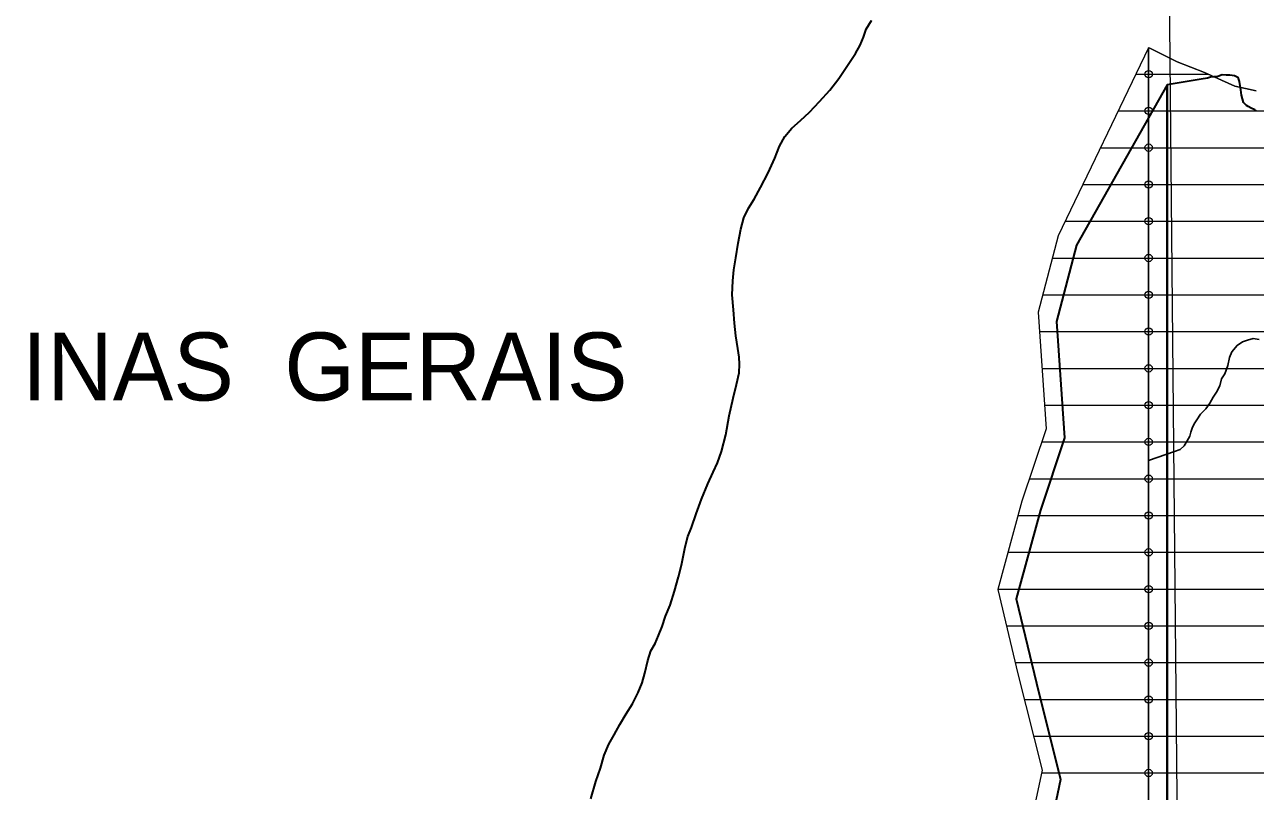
# Model space of a CAD drawing. Extents: x -10.5 to 30.8, y 18.4 to 58.7.
# Drawn here: x -1.4 to 5.3, y 50.15 to 54.32 of the extents above; entities that cross this region are included whole.
import ezdxf

# ---------------------------------------------------------------- set-up
doc = ezdxf.new("R2010")
doc.units = 0
doc.header["$LTSCALE"] = 0.08
doc.header["$PDMODE"] = 32
doc.header["$PDSIZE"] = 0.04
doc.linetypes.add('DASH_DOUBLE_DOT', pattern=[9.2, 5, -1.2, 0.3, -1.2, 0.3, -1.2])
for name, color, linetype, lineweight in [('20', 7, 'DASH_DOUBLE_DOT', 35), ('29', 7, 'Continuous', 13), ('43', 7, 'Continuous', 13), ('48', 7, 'Continuous', 35), ('52', 7, 'Continuous', 13), ('9', 7, 'Continuous', 25)]:
    doc.layers.add(name, color=color, linetype=linetype, lineweight=lineweight)
doc.layers.add('56', color=7, linetype='Continuous')

msp = doc.modelspace()

# ---------------------------------------------------------------- linework, layer by layer
at = {"layer": '20'}
msp.add_lwpolyline([(1.68376, 50.11473), (1.71233, 50.20779), (1.73621, 50.28075), (1.75763, 50.35117), (1.78172, 50.41162), (1.81099, 50.46217), (1.84269, 50.51775), (1.87687, 50.57588), (1.91108, 50.63151), (1.94271, 50.6921), (1.9644, 50.74501), (1.9786, 50.79779), (1.99502, 50.86562), (2.01171, 50.91844), (2.03364, 50.95885), (2.053, 51.00171), (2.07224, 51.05208), (2.0914, 51.10745), (2.11549, 51.16791), (2.13933, 51.24337), (2.16062, 51.32129), (2.17714, 51.38412), (2.18642, 51.42931), (2.19805, 51.48455), (2.2122, 51.53983), (2.23142, 51.5902), (2.25782, 51.6632), (2.28659, 51.74376), (2.32036, 51.82689), (2.34942, 51.88994), (2.37369, 51.94039), (2.39521, 52.00331), (2.41881, 52.09378), (2.43717, 52.19667), (2.45817, 52.29209), (2.47699, 52.36747), (2.491, 52.43025), (2.49272, 52.47782), (2.4921, 52.51533), (2.48377, 52.56272), (2.47256, 52.63258), (2.46642, 52.70001), (2.46019, 52.77246), (2.45379, 52.8549), (2.45756, 52.93002), (2.46158, 52.99013), (2.47304, 53.05537), (2.48677, 53.13567), (2.50056, 53.21095), (2.51708, 53.27378), (2.5413, 53.32674), (2.57313, 53.37482), (2.60722, 53.43795), (2.64855, 53.51872), (2.68489, 53.5969), (2.7114, 53.66241), (2.74065, 53.71545), (2.77753, 53.76111), (2.82454, 53.80195), (2.87398, 53.84784), (2.92822, 53.90632), (2.98494, 53.96734), (3.03408, 54.03073), (3.08058, 54.10158), (3.12467, 54.16739), (3.14901, 54.21284), (3.16838, 54.2557), (3.18274, 54.29848), (3.21204, 54.34652)], dxfattribs=at)
at = {"layer": '29'}
msp.add_lwpolyline([(3.21204, 54.34652), (3.18274, 54.29848), (3.16838, 54.2557), (3.14901, 54.21284), (3.12467, 54.16739), (3.08058, 54.10158), (3.03408, 54.03073), (2.98494, 53.96734), (2.92822, 53.90632), (2.87398, 53.84784), (2.82454, 53.80195), (2.77753, 53.76111), (2.74065, 53.71545), (2.7114, 53.66241), (2.68489, 53.5969), (2.64855, 53.51872), (2.60722, 53.43795), (2.57313, 53.37482), (2.5413, 53.32674), (2.51708, 53.27378), (2.50056, 53.21095), (2.48677, 53.13567), (2.47304, 53.05537), (2.46158, 52.99013), (2.45756, 52.93002), (2.45379, 52.8549), (2.46019, 52.77246), (2.46642, 52.70001), (2.47256, 52.63258), (2.48377, 52.56272), (2.4921, 52.51533), (2.49272, 52.47782), (2.491, 52.43025), (2.47699, 52.36747), (2.45817, 52.29209), (2.43717, 52.19667), (2.41881, 52.09378), (2.39521, 52.00331), (2.37369, 51.94039), (2.34942, 51.88994), (2.32036, 51.82689), (2.28659, 51.74376), (2.25782, 51.6632), (2.23142, 51.5902), (2.2122, 51.53983), (2.19805, 51.48455), (2.18642, 51.42931), (2.17714, 51.38412), (2.16062, 51.32129), (2.13933, 51.24337), (2.11549, 51.16791), (2.0914, 51.10745), (2.07224, 51.05208), (2.053, 51.00171), (2.03364, 50.95885), (2.01171, 50.91844), (1.99502, 50.86562), (1.9786, 50.79779), (1.9644, 50.74501), (1.94271, 50.6921), (1.91108, 50.63151), (1.87687, 50.57588), (1.84269, 50.51775), (1.81099, 50.46217), (1.78172, 50.41162), (1.75763, 50.35117), (1.73621, 50.28075), (1.71233, 50.20779), (1.68376, 50.11473)], dxfattribs=at)
at = {"layer": '29', "linetype": 'DASH_DOUBLE_DOT', "lineweight": 35}
msp.add_lwpolyline([(1.68376, 50.11473), (1.71233, 50.20779), (1.73621, 50.28075), (1.75763, 50.35117), (1.78172, 50.41162), (1.81099, 50.46217), (1.84269, 50.51775), (1.87687, 50.57588), (1.91108, 50.63151), (1.94271, 50.6921), (1.9644, 50.74501), (1.9786, 50.79779), (1.99502, 50.86562), (2.01171, 50.91844), (2.03364, 50.95885), (2.053, 51.00171), (2.07224, 51.05208), (2.0914, 51.10745), (2.11549, 51.16791), (2.13933, 51.24337), (2.16062, 51.32129), (2.17714, 51.38412), (2.18642, 51.42931), (2.19805, 51.48455), (2.2122, 51.53983), (2.23142, 51.5902), (2.25782, 51.6632), (2.28659, 51.74376), (2.32036, 51.82689), (2.34942, 51.88994), (2.37369, 51.94039), (2.39521, 52.00331), (2.41881, 52.09378), (2.43717, 52.19667), (2.45817, 52.29209), (2.47699, 52.36747), (2.491, 52.43025), (2.49272, 52.47782), (2.4921, 52.51533), (2.48377, 52.56272), (2.47256, 52.63258), (2.46642, 52.70001), (2.46019, 52.77246), (2.45379, 52.8549), (2.45756, 52.93002), (2.46158, 52.99013), (2.47304, 53.05537), (2.48677, 53.13567), (2.50056, 53.21095), (2.51708, 53.27378), (2.5413, 53.32674), (2.57313, 53.37482), (2.60722, 53.43795), (2.64855, 53.51872), (2.68489, 53.5969), (2.7114, 53.66241), (2.74065, 53.71545), (2.77753, 53.76111), (2.82454, 53.80195), (2.87398, 53.84784), (2.92822, 53.90632), (2.98494, 53.96734), (3.03408, 54.03073), (3.08058, 54.10158), (3.12467, 54.16739), (3.14901, 54.21284), (3.16838, 54.2557), (3.18274, 54.29848), (3.21204, 54.34652)], dxfattribs=at)
at = {"layer": '43'}
for p, q in [((4.719, 48.47183), (4.719, 54.19745)), ((4.719, 48.47183), (4.719, 54.19745)), ((4.65028, 54.0548), (4.719, 54.0548)), ((4.65028, 54.0548), (4.719, 54.0548)), ((4.719, 54.0548), (5.04063, 54.0548)), ((4.55392, 53.8548), (4.719, 53.8548)), ((4.55392, 53.8548), (4.719, 53.8548)), ((4.719, 53.8548), (7.38115, 53.8548)), ((4.45757, 53.6548), (4.719, 53.6548)), ((4.45757, 53.6548), (4.719, 53.6548)), ((4.719, 53.6548), (7.95638, 53.6548)), ((4.36122, 53.4548), (4.719, 53.4548)), ((4.36122, 53.4548), (4.719, 53.4548)), ((4.719, 53.4548), (8.42261, 53.4548)), ((4.26486, 53.2548), (4.719, 53.2548)), ((4.26486, 53.2548), (4.719, 53.2548)), ((4.719, 53.2548), (8.92708, 53.2548)), ((4.19484, 53.0548), (4.719, 53.0548)), ((4.19484, 53.0548), (4.719, 53.0548)), ((4.719, 53.0548), (9.91576, 53.0548)), ((4.14222, 52.8548), (4.719, 52.8548)), ((4.14222, 52.8548), (4.719, 52.8548)), ((4.719, 52.8548), (10.29326, 52.8548)), ((4.12456, 52.6548), (4.719, 52.6548)), ((4.12456, 52.6548), (4.719, 52.6548)), ((4.719, 52.6548), (11.74932, 52.6548)), ((4.13835, 52.4548), (4.719, 52.4548)), ((4.13835, 52.4548), (4.719, 52.4548)), ((4.719, 52.4548), (12.30135, 52.4548)), ((4.15214, 52.2548), (4.719, 52.2548)), ((4.15214, 52.2548), (4.719, 52.2548)), ((4.719, 52.2548), (12.92186, 52.2548)), ((4.1371, 52.0548), (4.719, 52.0548)), ((4.1371, 52.0548), (4.719, 52.0548)), ((4.719, 52.0548), (14.29713, 52.0548)), ((4.07045, 51.8548), (4.719, 51.8548)), ((4.07045, 51.8548), (4.719, 51.8548)), ((4.719, 51.8548), (15.2159, 51.8548)), ((4.00855, 51.6548), (4.719, 51.6548)), ((4.00855, 51.6548), (4.719, 51.6548)), ((4.719, 51.6548), (15.4387, 51.6548)), ((3.95401, 51.4548), (4.719, 51.4548)), ((3.95401, 51.4548), (4.719, 51.4548)), ((4.719, 51.4548), (15.65105, 51.4548)), ((3.89948, 51.2548), (4.719, 51.2548)), ((3.89948, 51.2548), (4.719, 51.2548)), ((4.719, 51.2548), (15.6669, 51.2548)), ((3.94594, 51.0548), (4.719, 51.0548)), ((3.94594, 51.0548), (4.719, 51.0548)), ((4.719, 51.0548), (15.6026, 51.0548)), ((3.99354, 50.8548), (4.719, 50.8548)), ((3.99354, 50.8548), (4.719, 50.8548)), ((4.719, 50.8548), (15.46322, 50.8548)), ((4.04281, 50.6548), (4.719, 50.6548)), ((4.04281, 50.6548), (4.719, 50.6548)), ((4.719, 50.6548), (15.23281, 50.6548)), ((4.09279, 50.4548), (4.719, 50.4548)), ((4.09279, 50.4548), (4.719, 50.4548)), ((4.719, 50.4548), (15.1383, 50.4548)), ((4.13608, 50.2548), (4.719, 50.2548)), ((4.13608, 50.2548), (4.719, 50.2548)), ((4.719, 50.2548), (15.00848, 50.2548))]:
    msp.add_line(p, q, dxfattribs=at)
for points in [[(4.719, 54.19745), (4.22652, 53.1752), (4.1173, 52.76008), (4.16099, 52.12647), (4.02993, 51.7332), (3.89886, 51.25254), (4.00808, 50.79372), (4.13914, 50.26936), (4.05177, 49.85424), (3.94255, 49.37357), (4.22652, 49.08954), (4.22652, 47.72402), (4.08453, 47.36352), (3.83333, 46.77361), (3.77873, 46.60975), (3.85518, 46.20555), (3.81149, 45.92152), (3.88794, 45.58287), (4.43403, 45.27699)], [(4.719, 54.19745), (4.22652, 53.1752), (4.1173, 52.76008), (4.16099, 52.12647), (4.02993, 51.7332), (3.89886, 51.25254), (4.00808, 50.79372), (4.13914, 50.26936), (4.05177, 49.85424), (3.94255, 49.37357), (4.22652, 49.08954), (4.22652, 47.72402), (4.08453, 47.36352), (3.83333, 46.77361), (3.77873, 46.60975), (3.85518, 46.20555), (3.81149, 45.92152), (3.88794, 45.58287), (4.43403, 45.27699)], [(4.719, 54.19745), (4.22652, 53.1752), (4.1173, 52.76008), (4.16099, 52.12647), (4.02993, 51.7332), (3.89886, 51.25254), (4.00808, 50.79372), (4.13914, 50.26936), (4.05177, 49.85424), (3.94255, 49.37357), (4.22652, 49.08954), (4.22652, 47.72402), (3.95893, 47.06856), (3.80603, 46.69168), (3.8004, 46.59979), (3.80803, 46.4548), (3.85518, 46.20555), (3.83333, 46.06354), (3.81149, 45.92152), (3.88794, 45.58287)], [(4.719, 54.19745), (4.22652, 53.1752), (4.1173, 52.76008), (4.16099, 52.12647), (4.02993, 51.7332), (3.89886, 51.25254), (4.00808, 50.79372), (4.13914, 50.26936), (4.05177, 49.85424), (3.94255, 49.37357), (4.22652, 49.08954), (4.22652, 47.72402), (3.95893, 47.06856), (3.80603, 46.69168), (3.8004, 46.59979), (3.80803, 46.4548), (3.85518, 46.20555), (3.83333, 46.06354), (3.81149, 45.92152), (3.88794, 45.58287)], [(4.43403, 45.27699), (4.719, 45.38561), (4.719, 54.19745), (4.719, 48.47183)], [(4.43403, 45.27699), (4.719, 45.38561), (4.719, 54.19745), (4.719, 48.47183)], [(5.30319, 53.96389), (5.18754, 53.98868), (5.02232, 54.06304), (4.87362, 54.12087), (4.72493, 54.19523), (4.719, 54.19745), (4.719, 48.47183)], [(5.30319, 53.96389), (5.18754, 53.98868), (5.02232, 54.06304), (4.87362, 54.12087), (4.72493, 54.19523), (4.719, 54.19745), (4.719, 48.47183)], [(4.719, 54.19745), (4.72493, 54.19523), (4.87362, 54.12087), (5.02232, 54.06304), (5.18754, 53.98868), (5.30319, 53.96389)], [(4.719, 54.19745), (4.72493, 54.19523), (4.87362, 54.12087), (5.02232, 54.06304), (5.18754, 53.98868), (5.30319, 53.96389)]]:
    msp.add_lwpolyline(points, dxfattribs=at)
for p in [(4.719, 54.0548), (4.719, 53.8548), (4.719, 53.6548), (4.719, 53.4548), (4.719, 53.2548), (4.719, 53.0548), (4.719, 52.8548), (4.719, 52.6548), (4.719, 52.4548), (4.719, 52.2548), (4.719, 52.0548), (4.719, 51.8548), (4.719, 51.6548), (4.719, 51.4548), (4.719, 51.2548), (4.719, 51.0548), (4.719, 50.8548), (4.719, 50.6548), (4.719, 50.4548), (4.719, 50.2548)]:
    msp.add_point(p, dxfattribs=at)
at = {"layer": '48'}
for p, q in [((4.819, 53.99619), (4.819, 41.93931)), ((4.819, 48.42183), (4.819, 53.99619))]:
    msp.add_line(p, q, dxfattribs=at)
for points in [[(5.30425, 53.85428), (5.29597, 53.86012), (5.27652, 53.86905), (5.25988, 53.87791), (5.2516, 53.88375), (5.23518, 53.90102), (5.22501, 53.94056), (5.22015, 53.96874), (5.21294, 54.01382), (5.20777, 54.03078), (5.20511, 54.03646), (5.18566, 54.0454), (5.16043, 54.04888), (5.14074, 54.04941), (5.11825, 54.05002), (5.09553, 54.04222), (5.05601, 54.03767), (5.03898, 54.03252), (5.00509, 54.02782), (4.819, 53.99619)], [(4.819, 53.99619), (4.32652, 53.1252), (4.2173, 52.71008), (4.26099, 52.07647), (4.12993, 51.6832), (3.99886, 51.20254), (4.10808, 50.74372), (4.23914, 50.21936), (4.15177, 49.80424), (4.04255, 49.32357), (4.32652, 49.03954), (4.32652, 47.67402), (4.18453, 47.31352), (3.93333, 46.72361), (3.87873, 46.55975), (3.95518, 46.15555), (3.91149, 45.87152), (3.98794, 45.53287), (4.53403, 45.22699)], [(4.53403, 45.22699), (4.819, 45.33561), (4.819, 53.99619), (4.819, 48.42183)]]:
    msp.add_lwpolyline(points, dxfattribs=at)
at = {"layer": '52'}
msp.add_lwpolyline([(4.79009, 58.74412), (4.82513, 55.08853), (4.87817, 49.55368), (4.93123, 44.01892), (4.98428, 38.48381), (5.03734, 32.94795), (5.09042, 27.4109), (5.14008, 22.22857)], dxfattribs=at)
at = {"layer": '9'}
msp.add_lwpolyline([(5.32034, 52.61116), (5.28779, 52.61633), (5.25766, 52.60898), (5.23003, 52.59912), (5.19982, 52.57928), (5.17203, 52.54441), (5.15931, 52.51448), (5.149, 52.46953), (5.13368, 52.4246), (5.11596, 52.39719), (5.1057, 52.35974), (5.08793, 52.32483), (5.07021, 52.29741), (5.05246, 52.265), (5.02971, 52.23512), (5.00194, 52.20526), (4.98171, 52.17536), (4.96652, 52.15293), (4.95636, 52.13049), (4.9487, 52.10802), (4.94355, 52.08555), (4.92834, 52.06062), (4.91313, 52.0332), (4.89044, 52.01331), (4.8603, 52.00347), (4.719, 51.95306)], dxfattribs=at)

# ---------------------------------------------------------------- texts
at = {"layer": '56'}
msp.add_text('MINAS  GERAIS', height=0.3694, dxfattribs=at).set_placement((-1.82177, 52.28028))

doc.saveas('drawing.dxf')
